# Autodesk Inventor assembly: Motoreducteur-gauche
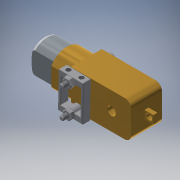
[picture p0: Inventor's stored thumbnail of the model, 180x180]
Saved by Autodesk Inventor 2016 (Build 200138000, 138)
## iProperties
Created: 2018-03
Part Number: Motoreducteur-gauche
Material: Générique
Document SubType Name: Assembly
Designer: Bruno
Author: Bruno
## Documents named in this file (6)
- D:\Cours\1-Cours-2017-18\2SI\projet\Inventor\Motoreducteur-gauche.iam
- D:\Cours\1-Cours-2017-18\2SI\projet\Inventor\reducteur.ipt
- D:\Cours\1-Cours-2017-18\2SI\projet\Inventor\moteur.ipt
- D:\Cours\1-Cours-2017-18\2SI\projet\Inventor\vis-M2.8.ipt
- D:\Cours\1-Cours-2017-18\2SI\projet\Inventor\Attache-moteur.ipt
- D:\Cours\1-Cours-2017-18\2SI\projet\Inventor\ecrou-M2.8.ipt
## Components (7 placed, 5 different names)
1. reducteur:1 — Placage:1, Placage:2, Angle:1, Placage:3, Placage:6, Placage:7, Placage:8, Logement:1
2. moteur:1 — Placage:1, Placage:2, Angle:1
3. vis-M2.8:1 — Placage:8, Placage:9, Logement:1, Placage:13
4. vis-M2.8:2 — Placage:6, Placage:7, Placage:10
5. Attache-moteur:1 — Placage:3, Placage:11, Placage:12, Placage:13
6. ecrou-M2.8:1 — Placage:10, Placage:12
7. ecrou-M2.8:2 — Placage:9, Placage:11
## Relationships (13: Mate 11, Angle 1, Insert 1)
- Placage:1 [Mate]: reducteur:1 ↔ moteur:1
- Placage:2 [Mate]: reducteur:1 ↔ moteur:1
- Angle:1: reducteur:1 ↔ moteur:1
- Placage:3 [Mate]: reducteur:1 ↔ Attache-moteur:1
- Placage:6 [Mate]: reducteur:1 ↔ vis-M2.8:2
- Placage:7 [Mate]: reducteur:1 ↔ vis-M2.8:2
- Placage:8 [Mate]: reducteur:1 ↔ vis-M2.8:1
- Placage:9 [Mate]: vis-M2.8:1 ↔ ecrou-M2.8:2
- Placage:10 [Mate]: vis-M2.8:2 ↔ ecrou-M2.8:1
- Placage:11 [Mate]: Attache-moteur:1 ↔ ecrou-M2.8:2
- Placage:12 [Mate]: Attache-moteur:1 ↔ ecrou-M2.8:1
- Logement:1 [Insert]: reducteur:1 ↔ vis-M2.8:1
- Placage:13 [Mate]: vis-M2.8:1 ↔ Attache-moteur:1
